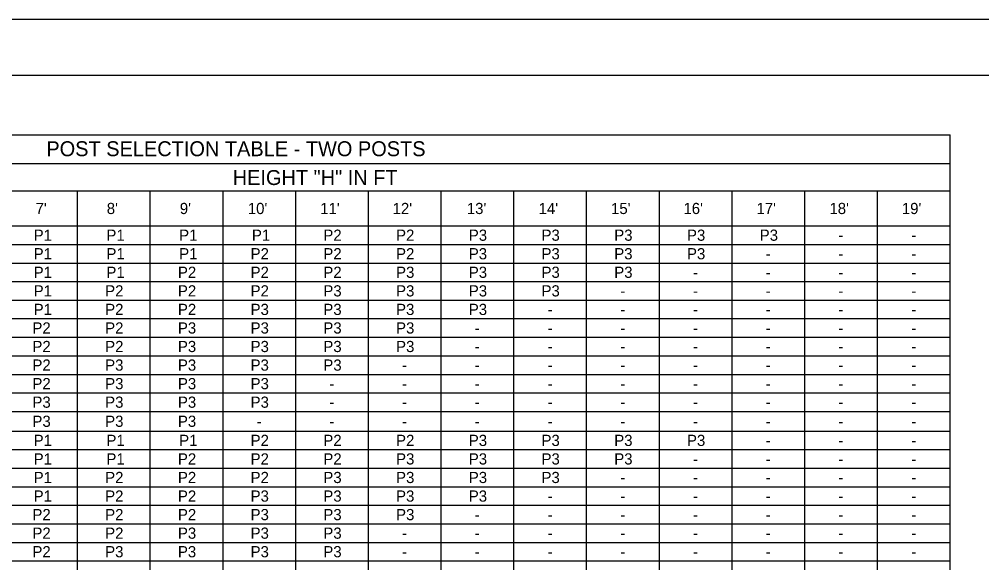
# Model space of a CAD drawing. Extents: x 637580 to 641008, y 294594 to 295782.
# Drawn here: x 638627 to 638885.2, y 295636 to 295781.6 of the extents above; entities that cross this region are included whole.
import ezdxf

# ---------------------------------------------------------------- set-up
doc = ezdxf.new("R2010")
doc.units = 0
for name, color, linetype in [('1', 7, 'Continuous'), ('2', 7, 'Continuous'), ('PLT-BNDY', 7, 'Continuous')]:
    doc.layers.add(name, color=color, linetype=linetype)

msp = doc.modelspace()

# ---------------------------------------------------------------- linework, layer by layer
at = {"layer": '1'}
for p, q in [((638461.31, 295766.63), (639247.31, 295766.63)), ((638509.81, 295750.63), (638876.73, 295750.63)), ((638876.73, 295231.34), (638876.73, 295750.63)), ((638509.81, 295742.95), (638876.73, 295742.95)), ((638642.64, 295231.34), (638642.64, 295735.61)), ((638662.15, 295231.34), (638662.15, 295735.61)), ((638681.66, 295231.34), (638681.66, 295735.61)), ((638701.17, 295231.34), (638701.17, 295735.61)), ((638720.67, 295231.34), (638720.67, 295735.61)), ((638740.18, 295231.34), (638740.18, 295735.61)), ((638759.69, 295231.34), (638759.69, 295735.61)), ((638779.2, 295231.34), (638779.2, 295735.61)), ((638798.7, 295231.34), (638798.7, 295735.61)), ((638818.21, 295231.34), (638818.21, 295735.61)), ((638837.72, 295231.34), (638837.72, 295735.61)), ((638857.23, 295231.34), (638857.23, 295735.61)), ((638509.81, 295726.25), (638876.73, 295726.25)), ((638509.81, 295671.26), (638876.73, 295671.26))]:
    msp.add_line(p, q, dxfattribs=at)
at = {"layer": '2'}
for p, q in [((638564.61, 295735.61), (638876.73, 295735.61)), ((638536.61, 295721.27), (638876.73, 295721.27)), ((638536.61, 295716.3), (638876.73, 295716.3)), ((638536.61, 295711.33), (638876.73, 295711.33)), ((638536.61, 295706.36), (638876.73, 295706.36)), ((638536.61, 295701.39), (638876.73, 295701.39)), ((638536.61, 295696.41), (638876.73, 295696.41)), ((638536.61, 295691.44), (638876.73, 295691.44)), ((638536.61, 295686.47), (638876.73, 295686.47)), ((638536.61, 295681.5), (638876.73, 295681.5)), ((638536.61, 295676.52), (638876.73, 295676.52)), ((638536.61, 295666.29), (638876.73, 295666.29)), ((638536.61, 295661.31), (638876.73, 295661.31)), ((638536.61, 295656.34), (638876.73, 295656.34)), ((638536.61, 295651.37), (638876.73, 295651.37)), ((638536.61, 295646.4), (638876.73, 295646.4)), ((638536.61, 295641.42), (638876.73, 295641.42)), ((638536.61, 295636.45), (638876.73, 295636.45))]:
    msp.add_line(p, q, dxfattribs=at)
at = {"layer": 'PLT-BNDY'}
msp.add_lwpolyline([(638421.31, 295781.63), (639262.31, 295781.63), (639262.31, 295187.63), (638421.31, 295187.63)], close=True, dxfattribs=at)

# ---------------------------------------------------------------- texts
at = {"layer": '1'}
for s, height, p in [('POST SELECTION TABLE - TWO POSTS', 4.003, (638634.27, 295744.93)), ('HEIGHT "H" IN FT', 4.003, (638684.25, 295737.21)), ("7'", 3, (638631.39, 295729.42)), ("8'", 3, (638650.48, 295729.42)), ("9'", 3, (638670.07, 295729.42)), ("10'", 3, (638688.31, 295729.42)), ("11'", 3, (638707.73, 295729.42)), ("12'", 3, (638727.15, 295729.42)), ("13'", 3, (638747.06, 295729.42)), ("14'", 3, (638766.32, 295729.42)), ("15'", 3, (638785.74, 295729.42)), ("16'", 3, (638805.16, 295729.42)), ("17'", 3, (638824.74, 295729.42)), ("18'", 3, (638844.32, 295729.42)), ("19'", 3, (638863.74, 295729.42)), ('P1', 3, (638630.88, 295722.26)), ('P1', 3, (638650.39, 295722.26)), ('P1', 3, (638669.9, 295722.26)), ('P1', 3, (638689.41, 295722.26)), ('P2', 3, (638708.57, 295722.26)), ('P2', 3, (638728.08, 295722.26)), ('P3', 3, (638747.59, 295722.26)), ('P3', 3, (638767.09, 295722.26)), ('P3', 3, (638786.6, 295722.26)), ('P3', 3, (638806.11, 295722.26)), ('P3', 3, (638825.62, 295722.26)), ('-', 3, (638846.74, 295722.26)), ('-', 3, (638866.25, 295722.26)), ('P1', 3, (638630.88, 295717.29)), ('P1', 3, (638650.39, 295717.29)), ('P1', 3, (638669.9, 295717.29)), ('P2', 3, (638689.06, 295717.29)), ('P2', 3, (638708.57, 295717.29)), ('P2', 3, (638728.08, 295717.29)), ('P3', 3, (638747.59, 295717.29)), ('P3', 3, (638767.09, 295717.29)), ('P3', 3, (638786.6, 295717.29)), ('P3', 3, (638806.11, 295717.29)), ('-', 3, (638827.23, 295717.29)), ('-', 3, (638846.74, 295717.29)), ('-', 3, (638866.25, 295717.29)), ('P1', 3, (638630.88, 295712.32)), ('P1', 3, (638650.39, 295712.32)), ('P2', 3, (638669.56, 295712.32)), ('P2', 3, (638689.06, 295712.32)), ('P2', 3, (638708.57, 295712.32)), ('P3', 3, (638728.08, 295712.32)), ('P3', 3, (638747.59, 295712.32)), ('P3', 3, (638767.09, 295712.32)), ('P3', 3, (638786.6, 295712.32)), ('-', 3, (638807.73, 295712.32)), ('-', 3, (638827.23, 295712.32)), ('-', 3, (638846.74, 295712.32)), ('-', 3, (638866.25, 295712.32)), ('P1', 3, (638630.88, 295707.34)), ('P2', 3, (638650.05, 295707.34)), ('P2', 3, (638669.56, 295707.34)), ('P2', 3, (638689.06, 295707.34)), ('P3', 3, (638708.57, 295707.34)), ('P3', 3, (638728.08, 295707.34)), ('P3', 3, (638747.59, 295707.34)), ('P3', 3, (638767.09, 295707.34)), ('-', 3, (638788.22, 295707.34)), ('-', 3, (638807.73, 295707.34)), ('-', 3, (638827.23, 295707.34)), ('-', 3, (638846.74, 295707.34)), ('-', 3, (638866.25, 295707.34)), ('P1', 3, (638630.88, 295702.37)), ('P2', 3, (638650.05, 295702.37)), ('P2', 3, (638669.56, 295702.37)), ('P3', 3, (638689.06, 295702.37)), ('P3', 3, (638708.57, 295702.37)), ('P3', 3, (638728.08, 295702.37)), ('P3', 3, (638747.59, 295702.37)), ('-', 3, (638768.71, 295702.37)), ('-', 3, (638788.22, 295702.37)), ('-', 3, (638807.73, 295702.37)), ('-', 3, (638827.23, 295702.37)), ('-', 3, (638846.74, 295702.37)), ('-', 3, (638866.25, 295702.37)), ('P2', 3, (638630.54, 295697.4)), ('P2', 3, (638650.05, 295697.4)), ('P3', 3, (638669.56, 295697.4)), ('P3', 3, (638689.06, 295697.4)), ('P3', 3, (638708.57, 295697.4)), ('P3', 3, (638728.08, 295697.4)), ('-', 3, (638749.2, 295697.4)), ('-', 3, (638768.71, 295697.4)), ('-', 3, (638788.22, 295697.4)), ('-', 3, (638807.73, 295697.4)), ('-', 3, (638827.23, 295697.4)), ('-', 3, (638846.74, 295697.4)), ('-', 3, (638866.25, 295697.4)), ('P2', 3, (638630.54, 295692.43)), ('P2', 3, (638650.05, 295692.43)), ('P3', 3, (638669.56, 295692.43)), ('P3', 3, (638689.06, 295692.43)), ('P3', 3, (638708.57, 295692.43)), ('P3', 3, (638728.08, 295692.43)), ('-', 3, (638749.2, 295692.43)), ('-', 3, (638768.71, 295692.43)), ('-', 3, (638788.22, 295692.43)), ('-', 3, (638807.73, 295692.43)), ('-', 3, (638827.23, 295692.43)), ('-', 3, (638846.74, 295692.43)), ('-', 3, (638866.25, 295692.43)), ('P2', 3, (638630.54, 295687.45)), ('P3', 3, (638650.05, 295687.45)), ('P3', 3, (638669.56, 295687.45)), ('P3', 3, (638689.06, 295687.45)), ('P3', 3, (638708.57, 295687.45)), ('-', 3, (638729.7, 295687.45)), ('-', 3, (638749.2, 295687.45)), ('-', 3, (638768.71, 295687.45)), ('-', 3, (638788.22, 295687.45)), ('-', 3, (638807.73, 295687.45)), ('-', 3, (638827.23, 295687.45)), ('-', 3, (638846.74, 295687.45)), ('-', 3, (638866.25, 295687.45)), ('P2', 3, (638630.54, 295682.48)), ('P3', 3, (638650.05, 295682.48)), ('P3', 3, (638669.56, 295682.48)), ('P3', 3, (638689.06, 295682.48)), ('-', 3, (638710.19, 295682.48)), ('-', 3, (638729.7, 295682.48)), ('-', 3, (638749.2, 295682.48)), ('-', 3, (638768.71, 295682.48)), ('-', 3, (638788.22, 295682.48)), ('-', 3, (638807.73, 295682.48)), ('-', 3, (638827.23, 295682.48)), ('-', 3, (638846.74, 295682.48)), ('-', 3, (638866.25, 295682.48)), ('P3', 3, (638630.54, 295677.51)), ('P3', 3, (638650.05, 295677.51)), ('P3', 3, (638669.56, 295677.51)), ('P3', 3, (638689.06, 295677.51)), ('-', 3, (638710.19, 295677.51)), ('-', 3, (638729.7, 295677.51)), ('-', 3, (638749.2, 295677.51)), ('-', 3, (638768.71, 295677.51)), ('-', 3, (638788.22, 295677.51)), ('-', 3, (638807.73, 295677.51)), ('-', 3, (638827.23, 295677.51)), ('-', 3, (638846.74, 295677.51)), ('-', 3, (638866.25, 295677.51)), ('P3', 3, (638630.54, 295672.39)), ('P3', 3, (638650.05, 295672.39)), ('P3', 3, (638669.56, 295672.39)), ('-', 3, (638690.68, 295672.39)), ('-', 3, (638710.19, 295672.39)), ('-', 3, (638729.7, 295672.39)), ('-', 3, (638749.2, 295672.39)), ('-', 3, (638768.71, 295672.39)), ('-', 3, (638788.22, 295672.39)), ('-', 3, (638807.73, 295672.39)), ('-', 3, (638827.23, 295672.39)), ('-', 3, (638846.74, 295672.39)), ('-', 3, (638866.25, 295672.39)), ('P1', 3, (638630.88, 295667.27)), ('P1', 3, (638650.39, 295667.27)), ('P1', 3, (638669.9, 295667.27)), ('P2', 3, (638689.06, 295667.27)), ('P2', 3, (638708.57, 295667.27)), ('P2', 3, (638728.08, 295667.27)), ('P3', 3, (638747.59, 295667.27)), ('P3', 3, (638767.09, 295667.27)), ('P3', 3, (638786.6, 295667.27)), ('P3', 3, (638806.11, 295667.27)), ('-', 3, (638827.23, 295667.27)), ('-', 3, (638846.74, 295667.27)), ('-', 3, (638866.25, 295667.27)), ('P1', 3, (638630.88, 295662.3)), ('P1', 3, (638650.39, 295662.3)), ('P2', 3, (638669.56, 295662.3)), ('P2', 3, (638689.06, 295662.3)), ('P2', 3, (638708.57, 295662.3)), ('P3', 3, (638728.08, 295662.3)), ('P3', 3, (638747.59, 295662.3)), ('P3', 3, (638767.09, 295662.3)), ('P3', 3, (638786.6, 295662.3)), ('-', 3, (638807.73, 295662.3)), ('-', 3, (638827.23, 295662.3)), ('-', 3, (638846.74, 295662.3)), ('-', 3, (638866.25, 295662.3)), ('P1', 3, (638630.88, 295657.33)), ('P2', 3, (638650.05, 295657.33)), ('P2', 3, (638669.56, 295657.33)), ('P2', 3, (638689.06, 295657.33)), ('P3', 3, (638708.57, 295657.33)), ('P3', 3, (638728.08, 295657.33)), ('P3', 3, (638747.59, 295657.33)), ('P3', 3, (638767.09, 295657.33)), ('-', 3, (638788.22, 295657.33)), ('-', 3, (638807.73, 295657.33)), ('-', 3, (638827.23, 295657.33)), ('-', 3, (638846.74, 295657.33)), ('-', 3, (638866.25, 295657.33)), ('P1', 3, (638630.88, 295652.35)), ('P2', 3, (638650.05, 295652.35)), ('P2', 3, (638669.56, 295652.35)), ('P3', 3, (638689.06, 295652.35)), ('P3', 3, (638708.57, 295652.35)), ('P3', 3, (638728.08, 295652.35)), ('P3', 3, (638747.59, 295652.35)), ('-', 3, (638768.71, 295652.35)), ('-', 3, (638788.22, 295652.35)), ('-', 3, (638807.73, 295652.35)), ('-', 3, (638827.23, 295652.35)), ('-', 3, (638846.74, 295652.35)), ('-', 3, (638866.25, 295652.35)), ('P2', 3, (638630.54, 295647.38)), ('P2', 3, (638650.05, 295647.38)), ('P2', 3, (638669.56, 295647.38)), ('P3', 3, (638689.06, 295647.38)), ('P3', 3, (638708.57, 295647.38)), ('P3', 3, (638728.08, 295647.38)), ('-', 3, (638749.2, 295647.38)), ('-', 3, (638768.71, 295647.38)), ('-', 3, (638788.22, 295647.38)), ('-', 3, (638807.73, 295647.38)), ('-', 3, (638827.23, 295647.38)), ('-', 3, (638846.74, 295647.38)), ('-', 3, (638866.25, 295647.38)), ('P2', 3, (638630.54, 295642.41)), ('P2', 3, (638650.05, 295642.41)), ('P3', 3, (638669.56, 295642.41)), ('P3', 3, (638689.06, 295642.41)), ('P3', 3, (638708.57, 295642.41)), ('-', 3, (638729.7, 295642.41)), ('-', 3, (638749.2, 295642.41)), ('-', 3, (638768.71, 295642.41)), ('-', 3, (638788.22, 295642.41)), ('-', 3, (638807.73, 295642.41)), ('-', 3, (638827.23, 295642.41)), ('-', 3, (638846.74, 295642.41)), ('-', 3, (638866.25, 295642.41)), ('P2', 3, (638630.54, 295637.44)), ('P3', 3, (638650.05, 295637.44)), ('P3', 3, (638669.56, 295637.44)), ('P3', 3, (638689.06, 295637.44)), ('P3', 3, (638708.57, 295637.44)), ('-', 3, (638729.7, 295637.44)), ('-', 3, (638749.2, 295637.44)), ('-', 3, (638768.71, 295637.44)), ('-', 3, (638788.22, 295637.44)), ('-', 3, (638807.73, 295637.44)), ('-', 3, (638827.23, 295637.44)), ('-', 3, (638846.74, 295637.44)), ('-', 3, (638866.25, 295637.44))]:
    msp.add_text(s, height=height, dxfattribs=at).set_placement(p)

doc.saveas('drawing.dxf')
